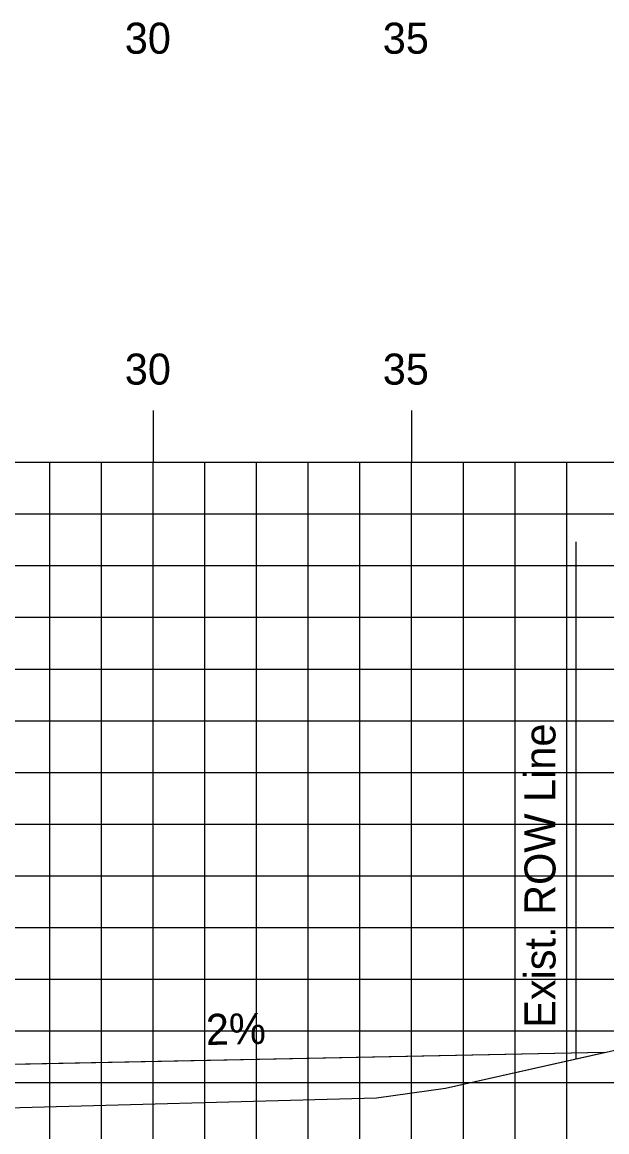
# Model space of a CAD drawing. Extents: x 853785 to 853955, y 366268 to 366378.
# Drawn here: x 853895.9 to 853907.21, y 366284.29 to 366305.75 of the extents above; entities that cross this region are included whole.
import ezdxf

# ---------------------------------------------------------------- set-up
doc = ezdxf.new("R2010")
doc.units = 0
for name, color, linetype in [('ANNOTATION', 7, 'Continuous'), ('D_Roadway_FinishedGrade', 7, 'Continuous'), ('E_ROW_Line', 7, 'Continuous'), ('H_V ANNOTATION', 7, 'Continuous'), ('JUNK FILL', 7, 'Continuous'), ('MAJOR', 7, 'Continuous'), ('MINOR', 7, 'Continuous'), ('S_Roadway_Centerline', 7, 'Continuous')]:
    doc.layers.add(name, color=color, linetype=linetype)

msp = doc.modelspace()

# ---------------------------------------------------------------- linework, layer by layer
at = {"layer": 'D_Roadway_FinishedGrade'}
msp.add_line((853907.158, 366285.817), (853892.443, 366285.522), dxfattribs=at)
at = {"layer": 'E_ROW_Line'}
msp.add_line((853906.618, 366285.696), (853906.618, 366295.696), dxfattribs=at)
at = {"layer": 'JUNK FILL'}
msp.add_lwpolyline([(853892.435, 366285.522), (853892.435, 366285.355), (853892.444, 366285.355), (853892.444, 366284.379), (853892.445, 366284.379), (853893.703, 366284.334), (853894.544, 366284.353), (853894.991, 366284.732), (853895.13, 366284.733), (853902.757, 366284.942), (853904.091, 366285.128), (853907.158, 366285.817), (853899.801, 366285.67), (853892.443, 366285.522)], close=True, dxfattribs=at)
at = {"layer": 'MAJOR'}
for p, q in [((853898.435, 366298.238), (853898.435, 366297.236)), ((853903.435, 366298.238), (853903.435, 366297.236)), ((853798.435, 366297.236), (853938.435, 366297.236)), ((853798.435, 366297.236), (853938.435, 366297.236)), ((853898.435, 366277.236), (853898.435, 366297.236)), ((853903.435, 366277.236), (853903.435, 366297.236)), ((853798.435, 366292.236), (853938.435, 366292.236)), ((853798.435, 366287.236), (853938.435, 366287.236))]:
    msp.add_line(p, q, dxfattribs=at)
at = {"layer": 'MINOR'}
for p, q in [((853896.435, 366277.236), (853896.435, 366297.236)), ((853897.435, 366277.236), (853897.435, 366297.236)), ((853899.435, 366277.236), (853899.435, 366297.236)), ((853900.435, 366277.236), (853900.435, 366297.236)), ((853901.435, 366277.236), (853901.435, 366297.236)), ((853902.435, 366277.236), (853902.435, 366297.236)), ((853904.435, 366277.236), (853904.435, 366297.236)), ((853905.435, 366277.236), (853905.435, 366297.236)), ((853906.435, 366277.236), (853906.435, 366297.236)), ((853798.435, 366296.236), (853938.435, 366296.236)), ((853798.435, 366295.236), (853938.435, 366295.236)), ((853798.435, 366294.236), (853938.435, 366294.236)), ((853798.435, 366293.236), (853938.435, 366293.236)), ((853798.435, 366291.236), (853938.435, 366291.236)), ((853798.435, 366290.236), (853938.435, 366290.236)), ((853798.435, 366289.236), (853938.435, 366289.236)), ((853798.435, 366288.236), (853938.435, 366288.236)), ((853798.435, 366286.236), (853938.435, 366286.236)), ((853798.435, 366285.236), (853938.435, 366285.236))]:
    msp.add_line(p, q, dxfattribs=at)
at = {"layer": 'S_Roadway_Centerline'}
msp.add_lwpolyline([(853837.576, 366284.644), (853850.621, 366285.197), (853857.775, 366285.567), (853862.721, 366285.439), (853868.661, 366285.302), (853871.998, 366285.204), (853882.091, 366284.926), (853892.253, 366284.386), (853893.703, 366284.334), (853894.544, 366284.353), (853894.551, 366284.361), (853894.991, 366284.732), (853895.13, 366284.733), (853902.757, 366284.942), (853904.091, 366285.128), (853909.786, 366286.408), (853911.32, 366286.334), (853918.965, 366286.226), (853919.002, 366286.986), (853919.212, 366288.09)], dxfattribs=at)

# ---------------------------------------------------------------- texts
at = {"layer": 'ANNOTATION'}
msp.add_text('2%', height=0.6, rotation=1.1484, dxfattribs=at).set_placement((853899.459, 366285.963))
at = {"layer": 'E_ROW_Line'}
msp.add_text('Exist. ROW Line', height=0.6, rotation=90, dxfattribs=at).set_placement((853906.218, 366286.296))
at = {"layer": 'H_V ANNOTATION'}
for s, p in [('30', (853897.884, 366305.136)), ('35', (853902.876, 366305.136)), ('30', (853897.884, 366298.736)), ('35', (853902.876, 366298.736))]:
    msp.add_text(s, height=0.6, dxfattribs=at).set_placement(p)

doc.saveas('drawing.dxf')
